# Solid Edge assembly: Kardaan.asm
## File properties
Author: Türk
Template: Iso Assembly.asm
Last saved by: Türk
Revision: 1
Application: Solid Edge
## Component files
kardaan.par
lliliigend.par
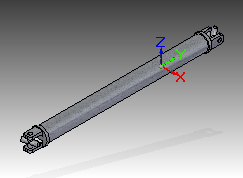
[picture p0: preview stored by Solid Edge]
